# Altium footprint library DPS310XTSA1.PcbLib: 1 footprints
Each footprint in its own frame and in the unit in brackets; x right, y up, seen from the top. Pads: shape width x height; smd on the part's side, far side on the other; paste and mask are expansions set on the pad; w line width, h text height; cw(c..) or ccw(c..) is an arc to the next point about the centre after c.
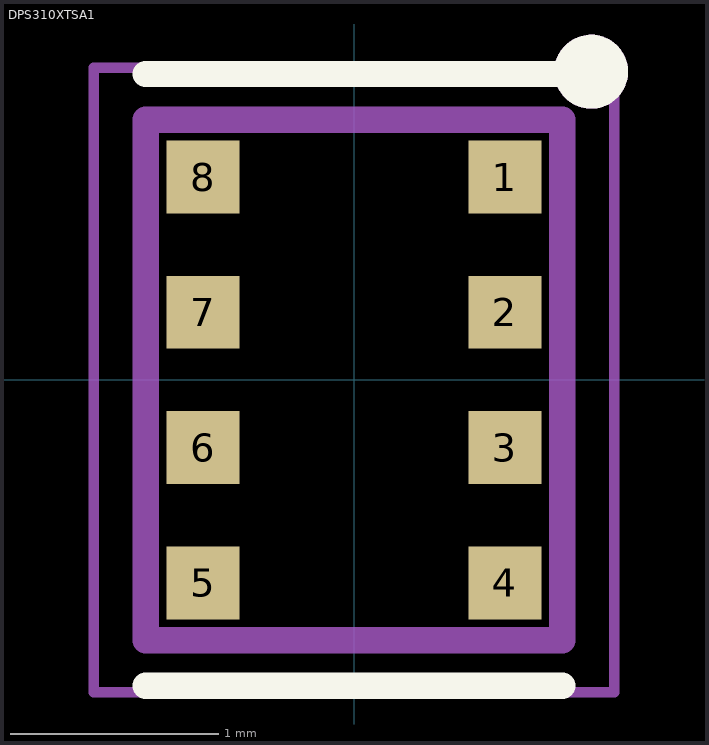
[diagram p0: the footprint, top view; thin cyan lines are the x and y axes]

## DPS310XTSA1 [mm]
pads (8):
  rect 0.35x0.35 smd paste-1: 1(0.725,0.975) 2(0.725,0.325) 3(0.725,-0.325) 4(0.725,-0.975) 5(-0.725,-0.975) 6(-0.725,-0.325) 7(-0.725,0.325) 8(-0.725,0.975)
Top Overlay:
  circle w0.203: c1.139,1.481 r0.076
  lines w0.127: -1,-1.47 1,-1.47 ; -1,1.47 1,1.47
Top Paste:
  circle w0.175: c0.725,-0.975 r0.088
  circle w0.175: c0.725,-0.325 r0.088
  circle w0.175: c0.725,0.325 r0.088
  circle w0.175: c0.725,0.975 r0.088
  circle w0.175: c-0.725,-0.975 r0.088
  circle w0.175: c-0.725,-0.325 r0.088
  circle w0.175: c-0.725,0.325 r0.088
  circle w0.175: c-0.725,0.975 r0.088
Mechanical 13:
  circle w0.203: c1.139,1.481 r0.076
  lines w0.127: -1,-1.25 1,-1.25 1,1.25 -1,1.25 -1,-1.25
Mechanical 15:
  lines w0.05: -1.25,-1.5 1.25,-1.5 1.25,1.5 -1.25,1.5 -1.25,-1.5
